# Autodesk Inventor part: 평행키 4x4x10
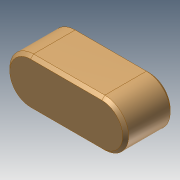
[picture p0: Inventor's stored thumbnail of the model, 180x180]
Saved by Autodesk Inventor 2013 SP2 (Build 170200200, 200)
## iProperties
Created: 2025-04
Part Number: 평행키 4x4x10
Material: Generic
Document SubType Name: Modeling
Designer: i
Density: 1 g/cm^3
Author: i
변환 표준: STEP AP214IS
전처리기: Build: 200, Release: 2013 SP2 Update 6 - Date: Thu 07/17/2014
전송 단위: 밀리미터
불확실성: 0.01
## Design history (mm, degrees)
node "평행키 4x4x101"
body "Solid1"
node "기준1"
